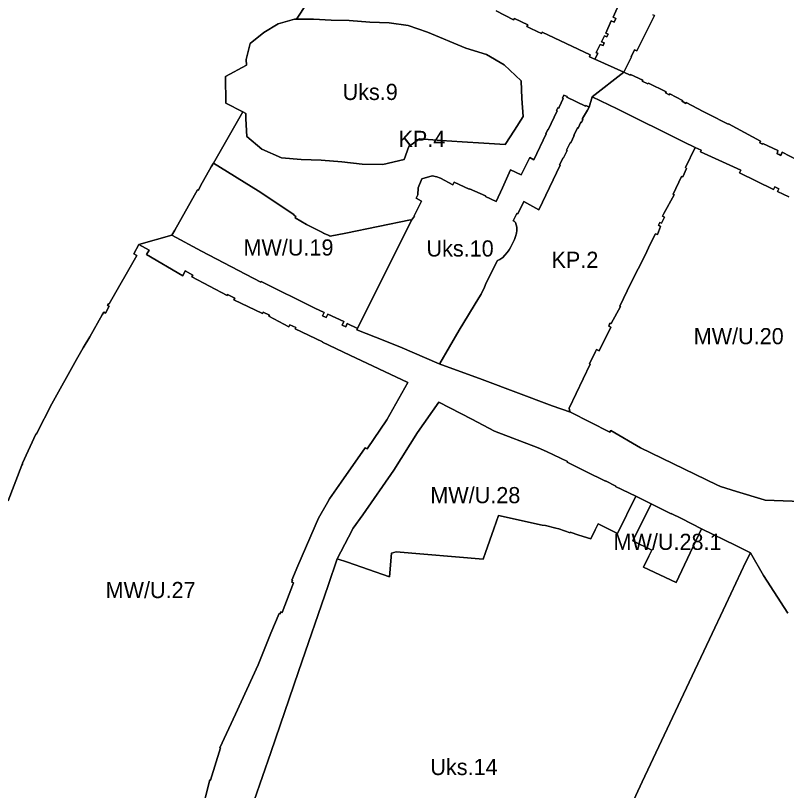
# Model space of a CAD drawing. Extents: x 7423367 to 7424726, y 5546744 to 5548391.
# Drawn here: x 7423955.4 to 7424194.2, y 5547600.8 to 5547840.8 of the extents above; entities that cross this region are included whole.
import ezdxf

# ---------------------------------------------------------------- set-up
doc = ezdxf.new("R2010")
doc.units = 0
doc.layers.add('linie_rozgraniczajace', color=7, linetype='Continuous')
doc.layers.add('oznaczenia_przeznaczen', color=7, linetype='Continuous')

msp = doc.modelspace()

# ---------------------------------------------------------------- linework, layer by layer
at = {"layer": 'linie_rozgraniczajace'}
for points in [[(7424059.01, 5547865.01), (7424042.47, 5547839.7), (7424041.79, 5547839.7), (7424036.76, 5547838.2), (7424032.36, 5547835.56), (7424028.08, 5547832.14), (7424026.89, 5547827.24), (7424026.97, 5547825.41), (7424020.48, 5547821.97), (7424020.57, 5547813.65), (7424025.84, 5547810.99), (7424016.7, 5547795.1), (7424016.02, 5547793.92), (7424012.71, 5547788.05), (7424012.06, 5547786.71), (7424011.81, 5547786.86), (7424004.72, 5547774.39), (7424003.86, 5547772.83), (7423993.65, 5547769.92), (7423992.03, 5547766.99), (7423993.01, 5547766.46), (7423984.4, 5547751.5), (7423984.25, 5547751.58), (7423983.92, 5547751.04), (7423984.38, 5547750.77), (7423983.24, 5547748.69), (7423982.75, 5547748.95), (7423982.24, 5547748.14), (7423978.39, 5547741.35), (7423976.39, 5547737.89), (7423974.27, 5547734.25), (7423966.62, 5547720.54), (7423962.01, 5547711.48), (7423961.83, 5547711.14), (7423961.7, 5547711.2), (7423957.55, 5547702.18), (7423957.68, 5547702.12), (7423957.42, 5547701.56), (7423953.17, 5547690.5)], [(7424104.24, 5547842.31), (7424109.63, 5547839.47), (7424109.89, 5547839.9), (7424114.03, 5547837.9), (7424113.79, 5547837.43), (7424114.8, 5547836.91), (7424116.96, 5547835.86), (7424118.28, 5547835.24), (7424118.46, 5547835.62), (7424133.4, 5547828.63), (7424133.12, 5547828.06), (7424134.83, 5547827.29), (7424143.77, 5547823.28), (7424134.02, 5547815.67), (7424133.01, 5547812.49), (7424132.03, 5547812.98), (7424131.91, 5547812.75), (7424126.12, 5547815.5), (7424126.23, 5547815.74), (7424125.25, 5547816.19), (7424124.77, 5547815.21), (7424125, 5547815.09), (7424123.76, 5547812.41), (7424123.64, 5547812.13), (7424123.37, 5547812.26), (7424122.93, 5547811.37), (7424123.17, 5547811.26), (7424120.35, 5547805.44), (7424120.28, 5547805.48), (7424119.66, 5547804.2), (7424119.72, 5547804.16), (7424115.89, 5547796.18), (7424114.67, 5547796.88), (7424111.97, 5547791.47), (7424108.72, 5547793.06), (7424106.2, 5547787.51), (7424104.22, 5547783.21), (7424100.91, 5547784.78), (7424100.98, 5547784.93), (7424095.99, 5547787.2), (7424095.94, 5547787.09), (7424091.21, 5547789.26), (7424090.89, 5547788.43), (7424087, 5547790.42), (7424085.9, 5547790.84), (7424084.46, 5547791.18), (7424081.24, 5547790.23), (7424080.11, 5547787.51), (7424079.99, 5547785.29), (7424079.47, 5547784.24), (7424081.17, 5547783.37), (7424078.89, 5547778.79), (7424079, 5547778.72), (7424078.03, 5547777.4), (7424077.71, 5547777.52), (7424057.67, 5547773.44), (7424052.87, 5547772.53), (7424052.54, 5547772.57), (7424052.59, 5547772.67), (7424050.66, 5547773.42), (7424050.72, 5547773.56), (7424045.54, 5547776.09), (7424042.04, 5547778.2), (7424042.21, 5547778.61), (7424041.62, 5547778.98), (7424041.67, 5547779.06), (7424033.86, 5547784.37), (7424030.55, 5547786.52), (7424016.7, 5547795.1), (7424025.84, 5547810.99), (7424026.79, 5547810.52), (7424026.7, 5547808.82), (7424027.08, 5547803.31), (7424031.68, 5547799.43), (7424037.75, 5547796.7), (7424043.92, 5547796.21), (7424050.03, 5547795.99), (7424056.51, 5547795.47), (7424062.8, 5547794.82), (7424069.19, 5547794.73), (7424075.8, 5547796.25), (7424077.21, 5547800.3), (7424080.56, 5547802.62), (7424087.28, 5547802.11), (7424093.71, 5547801.67), (7424100.4, 5547801.32), (7424107.09, 5547800.85), (7424109.94, 5547805.36), (7424112.59, 5547809.58), (7424112.18, 5547815.13), (7424112, 5547820.62), (7424106.72, 5547825.57), (7424101.24, 5547828.73), (7424094.88, 5547830.75), (7424083.02, 5547835.7), (7424077.01, 5547837.77), (7424071.14, 5547838.51), (7424065.18, 5547838.81), (7424058.78, 5547839.25), (7424053.14, 5547839.4), (7424047.68, 5547839.7), (7424042.47, 5547839.7), (7424059.01, 5547865.01)], [(7424142.09, 5547844.01), (7424140.46, 5547840.34), (7424141.35, 5547839.89), (7424140.77, 5547838.73), (7424139.91, 5547839.17), (7424138.17, 5547835.37), (7424138.96, 5547835), (7424138.57, 5547834.19), (7424137.76, 5547834.57), (7424136.88, 5547832.71), (7424137.72, 5547832.33), (7424137.37, 5547831.51), (7424136.5, 5547831.89), (7424135.17, 5547829.33), (7424135.7, 5547829.07), (7424134.83, 5547827.29), (7424133.12, 5547828.06), (7424133.4, 5547828.63), (7424118.46, 5547835.62), (7424118.28, 5547835.24), (7424116.96, 5547835.86), (7424114.8, 5547836.91), (7424113.79, 5547837.43), (7424114.03, 5547837.9), (7424109.89, 5547839.9), (7424109.63, 5547839.47), (7424104.24, 5547842.31)], [(7424152.81, 5547841.05), (7424153.29, 5547840.8), (7424147.81, 5547829.85), (7424147.14, 5547830.18), (7424146.05, 5547828.07), (7424146.21, 5547827.99), (7424143.77, 5547823.28), (7424134.83, 5547827.29), (7424135.7, 5547829.07), (7424135.17, 5547829.33), (7424136.5, 5547831.89), (7424137.37, 5547831.51), (7424137.72, 5547832.33), (7424136.88, 5547832.71), (7424137.76, 5547834.57), (7424138.57, 5547834.19), (7424138.96, 5547835), (7424138.17, 5547835.37), (7424139.91, 5547839.17), (7424140.77, 5547838.73), (7424141.35, 5547839.89), (7424140.46, 5547840.34), (7424142.09, 5547844.01)], [(7424197.55, 5547796.04), (7424192.84, 5547798.55), (7424192.36, 5547797.49), (7424191.84, 5547797.74), (7424191.25, 5547798.02), (7424191.51, 5547798.98), (7424186.81, 5547801.16), (7424186.72, 5547800.97), (7424186.27, 5547801.18), (7424185.88, 5547801.35), (7424186.11, 5547801.89), (7424176.2, 5547807.27), (7424176.14, 5547807.16), (7424169.97, 5547810.25), (7424168.35, 5547811.08), (7424163.13, 5547813.92), (7424162.96, 5547813.61), (7424162.17, 5547814.05), (7424161.84, 5547814.23), (7424162, 5547814.52), (7424158.02, 5547816.56), (7424157.86, 5547816.24), (7424156.72, 5547816.86), (7424156.86, 5547817.14), (7424151.41, 5547819.89), (7424151.26, 5547819.62), (7424149.46, 5547820.49), (7424149.62, 5547820.83), (7424145.87, 5547822.6), (7424145.7, 5547822.3), (7424143.77, 5547823.28), (7424146.21, 5547827.99), (7424146.05, 5547828.07), (7424147.14, 5547830.18), (7424147.81, 5547829.85), (7424153.29, 5547840.8), (7424152.81, 5547841.05)], [(7424194.83, 5547784.64), (7424191.33, 5547786.29), (7424191.77, 5547787.12), (7424190.53, 5547787.72), (7424190.17, 5547786.98), (7424179.56, 5547792.13), (7424179.97, 5547792.95), (7424167.51, 5547798.61), (7424167.73, 5547799.14), (7424165.84, 5547799.99), (7424162.31, 5547801.72), (7424141.69, 5547811.89), (7424134.02, 5547815.67), (7424143.77, 5547823.28), (7424145.7, 5547822.3), (7424145.87, 5547822.6), (7424149.62, 5547820.83), (7424149.46, 5547820.49), (7424151.26, 5547819.62), (7424151.41, 5547819.89), (7424156.86, 5547817.14), (7424156.72, 5547816.86), (7424157.86, 5547816.24), (7424158.02, 5547816.56), (7424162, 5547814.52), (7424161.84, 5547814.23), (7424162.17, 5547814.05), (7424162.96, 5547813.61), (7424163.13, 5547813.92), (7424168.35, 5547811.08), (7424169.97, 5547810.25), (7424176.14, 5547807.16), (7424176.2, 5547807.27), (7424186.11, 5547801.89), (7424185.88, 5547801.35), (7424186.27, 5547801.18), (7424186.72, 5547800.97), (7424186.81, 5547801.16), (7424191.51, 5547798.98), (7424191.25, 5547798.02), (7424191.84, 5547797.74), (7424192.36, 5547797.49), (7424192.84, 5547798.55), (7424197.55, 5547796.04)], [(7424204.31, 5547690.16), (7424187.51, 5547690.71), (7424187.28, 5547690.85), (7424178.67, 5547693.45), (7424173.76, 5547695), (7424172.61, 5547695.44), (7424148.95, 5547706.99), (7424139.76, 5547712.35), (7424139.46, 5547711.78), (7424127.32, 5547717.99), (7424127, 5547718.38), (7424126.92, 5547718.67), (7424126.89, 5547719.27), (7424133.38, 5547732.85), (7424133.17, 5547732.95), (7424135.02, 5547736.73), (7424135.33, 5547737.39), (7424136.13, 5547737.03), (7424139.75, 5547744.31), (7424139.1, 5547744.67), (7424139.38, 5547745.22), (7424139.56, 5547745.58), (7424139.87, 5547745.45), (7424142.71, 5547750.73), (7424142.53, 5547750.82), (7424145.99, 5547757.98), (7424150.45, 5547766.79), (7424151.89, 5547769.8), (7424153.61, 5547773.26), (7424154.18, 5547772.98), (7424155.1, 5547775.47), (7424154.52, 5547775.93), (7424154.9, 5547776.75), (7424155.49, 5547776.52), (7424156.33, 5547778.39), (7424155.79, 5547778.72), (7424156.21, 5547779.5), (7424159.41, 5547785.3), (7424159.07, 5547785.54), (7424161.61, 5547790.99), (7424162.02, 5547790.83), (7424163.24, 5547793.45), (7424162.87, 5547793.73), (7424165.84, 5547799.99), (7424167.73, 5547799.14), (7424167.51, 5547798.61), (7424179.97, 5547792.95), (7424179.56, 5547792.13), (7424190.17, 5547786.98), (7424190.53, 5547787.72), (7424191.77, 5547787.12), (7424191.33, 5547786.29), (7424194.83, 5547784.64)], [(7424012.85, 5547593.23), (7424015.6, 5547604.09), (7424015.75, 5547604.05), (7424018.9, 5547614.03), (7424018.72, 5547614.09), (7424023.58, 5547624.5), (7424030.52, 5547639.78), (7424034.53, 5547649.54), (7424037.11, 5547655.69), (7424037.37, 5547655.59), (7424037.57, 5547656.11), (7424038, 5547655.94), (7424041.45, 5547665.13), (7424041.01, 5547665.32), (7424041.23, 5547665.84), (7424041, 5547665.92), (7424042.84, 5547670.43), (7424049.2, 5547685.18), (7424052.02, 5547690.02), (7424052.68, 5547691.15), (7424056.24, 5547696.35), (7424063.67, 5547706.96), (7424064.32, 5547706.61), (7424070.44, 5547715.64), (7424076.88, 5547727.15), (7424058.99, 5547735.66), (7424050.48, 5547739.7), (7424050.52, 5547739.78), (7424041.99, 5547743.83), (7424042.19, 5547744.16), (7424040.35, 5547745.02), (7424040.07, 5547744.45), (7424033.86, 5547747.68), (7424034.02, 5547748.04), (7424032.1, 5547748.94), (7424031.87, 5547748.51), (7424023.07, 5547752.76), (7424023.33, 5547753.28), (7424021.11, 5547754.4), (7424020.96, 5547754.07), (7424010.06, 5547759.87), (7424010.33, 5547760.4), (7424007.95, 5547761.73), (7424007.19, 5547760.25), (7423995.98, 5547766.8), (7423996.84, 5547768.15), (7423993.65, 5547769.92), (7424003.86, 5547772.83), (7424012.98, 5547767.85), (7424031.35, 5547758.29), (7424031.48, 5547758.5), (7424048.08, 5547750.2), (7424050.98, 5547748.85), (7424050.49, 5547747.78), (7424051.57, 5547747.28), (7424052.09, 5547748.34), (7424057.04, 5547746.02), (7424056.59, 5547744.96), (7424057.74, 5547744.46), (7424058.14, 5547745.4), (7424061.27, 5547743.93), (7424061.1, 5547743.5), (7424066.94, 5547741.25), (7424074.39, 5547738.26), (7424086.59, 5547732.98), (7424099.92, 5547728.07), (7424121.55, 5547719.9), (7424127.32, 5547717.99), (7424139.46, 5547711.78), (7424139.76, 5547712.35), (7424148.95, 5547706.99), (7424172.61, 5547695.44), (7424173.76, 5547695), (7424178.67, 5547693.45), (7424187.28, 5547690.85), (7424187.51, 5547690.71), (7424204.31, 5547690.16)], [(7423953.17, 5547690.5), (7423957.42, 5547701.56), (7423957.68, 5547702.12), (7423957.55, 5547702.18), (7423961.7, 5547711.2), (7423961.83, 5547711.14), (7423962.01, 5547711.48), (7423966.62, 5547720.54), (7423974.27, 5547734.25), (7423976.39, 5547737.89), (7423978.39, 5547741.35), (7423982.24, 5547748.14), (7423982.75, 5547748.95), (7423983.24, 5547748.69), (7423984.38, 5547750.77), (7423983.92, 5547751.04), (7423984.25, 5547751.58), (7423984.4, 5547751.5), (7423993.01, 5547766.46), (7423992.03, 5547766.99), (7423993.65, 5547769.92), (7423996.84, 5547768.15), (7423995.98, 5547766.8), (7424007.19, 5547760.25), (7424007.95, 5547761.73), (7424010.33, 5547760.4), (7424010.06, 5547759.87), (7424020.96, 5547754.07), (7424021.11, 5547754.4), (7424023.33, 5547753.28), (7424023.07, 5547752.76), (7424031.87, 5547748.51), (7424032.1, 5547748.94), (7424034.02, 5547748.04), (7424033.86, 5547747.68), (7424040.07, 5547744.45), (7424040.35, 5547745.02), (7424042.19, 5547744.16), (7424041.99, 5547743.83), (7424050.52, 5547739.78), (7424050.48, 5547739.7), (7424058.99, 5547735.66), (7424076.88, 5547727.15), (7424070.44, 5547715.64), (7424064.32, 5547706.61), (7424063.67, 5547706.96), (7424056.24, 5547696.35), (7424052.68, 5547691.15), (7424052.02, 5547690.02), (7424049.2, 5547685.18), (7424042.84, 5547670.43), (7424041, 5547665.92), (7424041.23, 5547665.84), (7424041.01, 5547665.32), (7424041.45, 5547665.13), (7424038, 5547655.94), (7424037.57, 5547656.11), (7424037.37, 5547655.59), (7424037.11, 5547655.69), (7424034.53, 5547649.54), (7424030.52, 5547639.78), (7424023.58, 5547624.5), (7424018.72, 5547614.09), (7424018.9, 5547614.03), (7424015.75, 5547604.05), (7424015.6, 5547604.09), (7424012.85, 5547593.23)], [(7424194.57, 5547655.72), (7424187.08, 5547667.38), (7424182.98, 5547674.43), (7424178.52, 5547676.7), (7424167.82, 5547681.87), (7424161.6, 5547685.01), (7424161.62, 5547685.06), (7424158.48, 5547686.61), (7424158.42, 5547686.54), (7424152.22, 5547689.61), (7424147.48, 5547691.94), (7424141.22, 5547695.02), (7424141.26, 5547695.1), (7424138.12, 5547696.7), (7424138.08, 5547696.63), (7424131.98, 5547699.66), (7424126.2, 5547702.53), (7424126.31, 5547702.73), (7424119.8, 5547705.83), (7424117.21, 5547706.92), (7424103.78, 5547712.12), (7424096.75, 5547715.83), (7424086.52, 5547721.1), (7424079.89, 5547711.68), (7424072.54, 5547699.98), (7424062.94, 5547686.19), (7424060.01, 5547682.1), (7424058.52, 5547679.33), (7424055.05, 5547672.57), (7424052.24, 5547664.29), (7424043.1, 5547637.68), (7424034.47, 5547612.64), (7424029.34, 5547597.71)], [(7424029.34, 5547597.71), (7424034.47, 5547612.64), (7424043.1, 5547637.68), (7424052.24, 5547664.29), (7424055.05, 5547672.57), (7424058.24, 5547671.53), (7424071.23, 5547667.01), (7424071.88, 5547674.32), (7424073.26, 5547674.71), (7424100.2, 5547672.42), (7424100.93, 5547674.49), (7424103.55, 5547681.89), (7424105.01, 5547686.04), (7424118.54, 5547682.95), (7424119.57, 5547682.88), (7424122.71, 5547682.1), (7424123.65, 5547681.81), (7424127.13, 5547680.65), (7424127.18, 5547680.79), (7424129.87, 5547679.92), (7424133.57, 5547678.73), (7424134.91, 5547681.56), (7424135.8, 5547683.42), (7424141.81, 5547680.43), (7424147.48, 5547691.94), (7424152.22, 5547689.61), (7424146.54, 5547678.17), (7424152.45, 5547675.23), (7424151.51, 5547673.4), (7424149.83, 5547670.03), (7424159.99, 5547665.29), (7424167.82, 5547681.87), (7424178.52, 5547676.7), (7424182.98, 5547674.43), (7424181.58, 5547671.67), (7424175.4, 5547658.46), (7424170.31, 5547647.69), (7424164.05, 5547634.41), (7424149.46, 5547603.55), (7424139.65, 5547582.36)], [(7424195.66, 5547530.98), (7424192.95, 5547527.74), (7424190.84, 5547525.79), (7424188.35, 5547524.59), (7424185.9, 5547524.15), (7424181.26, 5547522.91), (7424173.95, 5547523.61), (7424164.06, 5547524.68), (7424150.95, 5547526.11), (7424132.54, 5547527.94), (7424114.69, 5547529.61), (7424122.98, 5547547.25), (7424139.65, 5547582.36), (7424149.46, 5547603.55), (7424164.05, 5547634.41), (7424170.31, 5547647.69), (7424175.4, 5547658.46), (7424181.58, 5547671.67), (7424182.98, 5547674.43), (7424187.08, 5547667.38), (7424194.57, 5547655.72)]]:
    msp.add_lwpolyline(points, dxfattribs=at)
for points in [[(7424020.57, 5547813.65), (7424020.48, 5547821.97), (7424026.97, 5547825.41), (7424026.89, 5547827.24), (7424028.08, 5547832.14), (7424032.36, 5547835.56), (7424036.76, 5547838.2), (7424041.79, 5547839.7), (7424042.47, 5547839.7), (7424047.68, 5547839.7), (7424053.14, 5547839.4), (7424058.78, 5547839.25), (7424065.18, 5547838.81), (7424071.14, 5547838.51), (7424077.01, 5547837.77), (7424083.02, 5547835.7), (7424094.88, 5547830.75), (7424101.24, 5547828.73), (7424106.72, 5547825.57), (7424112, 5547820.62), (7424112.18, 5547815.13), (7424112.59, 5547809.58), (7424109.94, 5547805.36), (7424107.09, 5547800.85), (7424100.4, 5547801.32), (7424093.71, 5547801.67), (7424087.28, 5547802.11), (7424080.56, 5547802.62), (7424077.21, 5547800.3), (7424075.8, 5547796.25), (7424069.19, 5547794.73), (7424062.8, 5547794.82), (7424056.51, 5547795.47), (7424050.03, 5547795.99), (7424043.92, 5547796.21), (7424037.75, 5547796.7), (7424031.68, 5547799.43), (7424027.08, 5547803.31), (7424026.7, 5547808.82), (7424026.79, 5547810.52), (7424025.84, 5547810.99)], [(7424061.1, 5547743.5), (7424061.27, 5547743.93), (7424078.03, 5547777.4), (7424079, 5547778.72), (7424078.89, 5547778.79), (7424081.17, 5547783.37), (7424079.47, 5547784.24), (7424079.99, 5547785.29), (7424080.11, 5547787.51), (7424081.24, 5547790.23), (7424084.46, 5547791.18), (7424085.9, 5547790.84), (7424087, 5547790.42), (7424090.89, 5547788.43), (7424091.21, 5547789.26), (7424095.94, 5547787.09), (7424095.99, 5547787.2), (7424100.98, 5547784.93), (7424100.91, 5547784.78), (7424104.22, 5547783.21), (7424106.2, 5547787.51), (7424108.72, 5547793.06), (7424111.97, 5547791.47), (7424114.67, 5547796.88), (7424115.89, 5547796.18), (7424119.72, 5547804.16), (7424119.66, 5547804.2), (7424120.28, 5547805.48), (7424120.35, 5547805.44), (7424123.17, 5547811.26), (7424122.93, 5547811.37), (7424123.37, 5547812.26), (7424123.64, 5547812.13), (7424123.76, 5547812.41), (7424125, 5547815.09), (7424124.77, 5547815.21), (7424125.25, 5547816.19), (7424126.23, 5547815.74), (7424126.12, 5547815.5), (7424131.91, 5547812.75), (7424132.03, 5547812.98), (7424133.01, 5547812.49), (7424132.55, 5547811.51), (7424131.02, 5547808.98), (7424130.87, 5547808.71), (7424131.13, 5547808.58), (7424130.72, 5547807.65), (7424130.45, 5547807.78), (7424129.61, 5547805.93), (7424129.44, 5547806.02), (7424128.29, 5547803.7), (7424128.46, 5547803.62), (7424127.38, 5547801.35), (7424127.21, 5547801.43), (7424126.08, 5547799.12), (7424126.24, 5547799.03), (7424125.14, 5547796.73), (7424124.99, 5547796.8), (7424123.91, 5547794.6), (7424124.07, 5547794.52), (7424117.45, 5547780.69), (7424112.87, 5547783.18), (7424110.98, 5547779.4), (7424110.68, 5547779.55), (7424109.53, 5547777.28), (7424109.82, 5547777.14), (7424110.21, 5547776.68), (7424110.68, 5547775.26), (7424110.67, 5547774.25), (7424110.53, 5547773.39), (7424110.27, 5547772.42), (7424109.96, 5547771.49), (7424109.57, 5547770.63), (7424109.13, 5547769.76), (7424108.73, 5547769.03), (7424108.24, 5547768.22), (7424107.68, 5547767.44), (7424106.95, 5547766.57), (7424106.28, 5547765.93), (7424105.36, 5547765.27), (7424104.66, 5547764.92), (7424101.15, 5547758.04), (7424100.63, 5547756.68), (7424099.57, 5547754.55), (7424098.85, 5547753.35), (7424092.76, 5547743.39), (7424086.82, 5547733.03), (7424086.59, 5547732.98), (7424074.39, 5547738.26), (7424066.94, 5547741.25)], [(7424086.59, 5547732.98), (7424086.82, 5547733.03), (7424092.76, 5547743.39), (7424098.85, 5547753.35), (7424099.57, 5547754.55), (7424100.63, 5547756.68), (7424101.15, 5547758.04), (7424104.66, 5547764.92), (7424105.36, 5547765.27), (7424106.28, 5547765.93), (7424106.95, 5547766.57), (7424107.68, 5547767.44), (7424108.24, 5547768.22), (7424108.73, 5547769.03), (7424109.13, 5547769.76), (7424109.57, 5547770.63), (7424109.96, 5547771.49), (7424110.27, 5547772.42), (7424110.53, 5547773.39), (7424110.67, 5547774.25), (7424110.68, 5547775.26), (7424110.21, 5547776.68), (7424109.82, 5547777.14), (7424109.53, 5547777.28), (7424110.68, 5547779.55), (7424110.98, 5547779.4), (7424112.87, 5547783.18), (7424117.45, 5547780.69), (7424124.07, 5547794.52), (7424123.91, 5547794.6), (7424124.99, 5547796.8), (7424125.14, 5547796.73), (7424126.24, 5547799.03), (7424126.08, 5547799.12), (7424127.21, 5547801.43), (7424127.38, 5547801.35), (7424128.46, 5547803.62), (7424128.29, 5547803.7), (7424129.44, 5547806.02), (7424129.61, 5547805.93), (7424130.45, 5547807.78), (7424130.72, 5547807.65), (7424131.13, 5547808.58), (7424130.87, 5547808.71), (7424131.02, 5547808.98), (7424132.55, 5547811.51), (7424133.01, 5547812.49), (7424134.02, 5547815.67), (7424141.69, 5547811.89), (7424162.31, 5547801.72), (7424165.84, 5547799.99), (7424162.87, 5547793.73), (7424163.24, 5547793.45), (7424162.02, 5547790.83), (7424161.61, 5547790.99), (7424159.07, 5547785.54), (7424159.41, 5547785.3), (7424156.21, 5547779.5), (7424155.79, 5547778.72), (7424156.33, 5547778.39), (7424155.49, 5547776.52), (7424154.9, 5547776.75), (7424154.52, 5547775.93), (7424155.1, 5547775.47), (7424154.18, 5547772.98), (7424153.61, 5547773.26), (7424151.89, 5547769.8), (7424150.45, 5547766.79), (7424145.99, 5547757.98), (7424142.53, 5547750.82), (7424142.71, 5547750.73), (7424139.87, 5547745.45), (7424139.56, 5547745.58), (7424139.38, 5547745.22), (7424139.1, 5547744.67), (7424139.75, 5547744.31), (7424136.13, 5547737.03), (7424135.33, 5547737.39), (7424135.02, 5547736.73), (7424133.17, 5547732.95), (7424133.38, 5547732.85), (7424126.89, 5547719.27), (7424126.92, 5547718.67), (7424127, 5547718.38), (7424127.32, 5547717.99), (7424121.55, 5547719.9), (7424099.92, 5547728.07)], [(7424003.86, 5547772.83), (7424004.72, 5547774.39), (7424011.81, 5547786.86), (7424012.06, 5547786.71), (7424012.71, 5547788.05), (7424016.02, 5547793.92), (7424016.7, 5547795.1), (7424030.55, 5547786.52), (7424033.86, 5547784.37), (7424041.67, 5547779.06), (7424041.62, 5547778.98), (7424042.21, 5547778.61), (7424042.04, 5547778.2), (7424045.54, 5547776.09), (7424050.72, 5547773.56), (7424050.66, 5547773.42), (7424052.59, 5547772.67), (7424052.54, 5547772.57), (7424052.87, 5547772.53), (7424057.67, 5547773.44), (7424077.71, 5547777.52), (7424078.03, 5547777.4), (7424061.27, 5547743.93), (7424058.14, 5547745.4), (7424057.74, 5547744.46), (7424056.59, 5547744.96), (7424057.04, 5547746.02), (7424052.09, 5547748.34), (7424051.57, 5547747.28), (7424050.49, 5547747.78), (7424050.98, 5547748.85), (7424048.08, 5547750.2), (7424031.48, 5547758.5), (7424031.35, 5547758.29), (7424012.98, 5547767.85)], [(7424055.05, 5547672.57), (7424058.52, 5547679.33), (7424060.01, 5547682.1), (7424062.94, 5547686.19), (7424072.54, 5547699.98), (7424079.89, 5547711.68), (7424086.52, 5547721.1), (7424096.75, 5547715.83), (7424103.78, 5547712.12), (7424117.21, 5547706.92), (7424119.8, 5547705.83), (7424126.31, 5547702.73), (7424126.2, 5547702.53), (7424131.98, 5547699.66), (7424138.08, 5547696.63), (7424138.12, 5547696.7), (7424141.26, 5547695.1), (7424141.22, 5547695.02), (7424147.48, 5547691.94), (7424141.81, 5547680.43), (7424135.8, 5547683.42), (7424134.91, 5547681.56), (7424133.57, 5547678.73), (7424129.87, 5547679.92), (7424127.18, 5547680.79), (7424127.13, 5547680.65), (7424123.65, 5547681.81), (7424122.71, 5547682.1), (7424119.57, 5547682.88), (7424118.54, 5547682.95), (7424105.01, 5547686.04), (7424103.55, 5547681.89), (7424100.93, 5547674.49), (7424100.2, 5547672.42), (7424073.26, 5547674.71), (7424071.88, 5547674.32), (7424071.23, 5547667.01), (7424058.24, 5547671.53)], [(7424146.54, 5547678.17), (7424152.22, 5547689.61), (7424158.42, 5547686.54), (7424158.48, 5547686.61), (7424161.62, 5547685.06), (7424161.6, 5547685.01), (7424167.82, 5547681.87), (7424159.99, 5547665.29), (7424149.83, 5547670.03), (7424151.51, 5547673.4), (7424152.45, 5547675.23)]]:
    msp.add_lwpolyline(points, close=True, dxfattribs=at)

# ---------------------------------------------------------------- texts
at = {"layer": 'oznaczenia_przeznaczen'}
for s, p in [('Uks.9', (7424056.7, 5547814.66)), ('KP.4', (7424074.02, 5547800.11)), ('MW/U.19', (7424026.02, 5547766.49)), ('Uks.10', (7424082.68, 5547766.19)), ('KP.2', (7424121.39, 5547762.68)), ('MW/U.20', (7424165.43, 5547739.03)), ('MW/U.28', (7424083.87, 5547689.8)), ('MW/U.28.1', (7424140.6, 5547675.33)), ('MW/U.27', (7423983.32, 5547660.41)), ('Uks.14', (7424083.88, 5547605.61))]:
    msp.add_text(s, height=5, dxfattribs=at).set_placement(p)

doc.saveas('drawing.dxf')
